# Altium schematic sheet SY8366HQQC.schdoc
size 127 x 101 mm
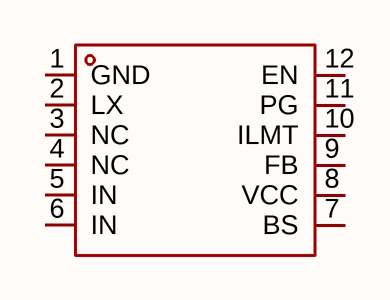
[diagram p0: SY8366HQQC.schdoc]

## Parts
U?  sy8366hqqc  [QFN-12_L3.0-W3.0-P0.45-TL-EP]  (value not drawn)

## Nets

Not connected (* = marked no-connect by the designer): U? 1(GND) 2(LX) 3(NC) 4(NC) 5(IN) 6(IN) 7(BS) 8(VCC) 9(FB) 10(ILMT) 11(PG) 12(EN)

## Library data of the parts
U? = sy8366hqqc: 功能类型:降压型;工作电压:4V~28V;输出电压:5V;输出电流:6A;输出类型:固定;; Manufacturer: Silergy(矽力杰); AddInBom: yes; ModelId: 1bffed05a99840398d20192cfba0066b; ModelTransform: 118.8974,118.5037,0,0,0,0,-0.591,-6.614,0; Function: 降压型; Voltage - Supply: 4V~28V; Output Voltage: 5V; Output Current: 6A; Frequency - Switching: 800kHz; Synchronous Rectifier: 是; Number of Outputs: 1; Topology: 降压式; Quiescent Current: 100uA; Switch tube (built-in/external): 内置; Output Type: 固定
